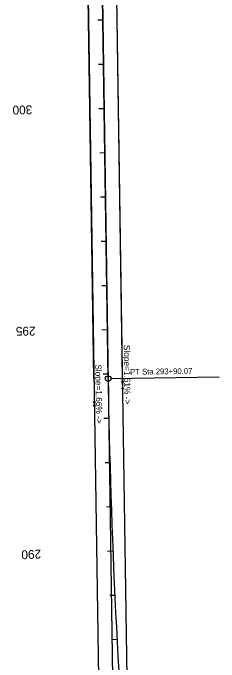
# Model space of a CAD drawing. Extents: x 5180909 to 5237144, y 3695282 to 3720102.
# Drawn here: x 5196575 to 5197040, y 3712197 to 3713664 of the extents above; entities that cross this region are included whole.
import ezdxf

# ---------------------------------------------------------------- set-up
doc = ezdxf.new("R2010")
doc.units = 0
for name, color, linetype in [('Alignment', 7, 'Continuous'), ('Default', 7, 'Continuous'), ('DisFieldPoint', 7, 'Continuous'), ('dsnEntrancePaved', 7, 'Continuous'), ('dsnShadingGranular', 7, 'Continuous'), ('dsnSidewalkShadingRamp', 7, 'Continuous')]:
    doc.layers.add(name, color=color, linetype=linetype)

msp = doc.modelspace()

# ---------------------------------------------------------------- linework, layer by layer
at = {"layer": 'Alignment'}
msp.add_line((5196789.7, 3712837.6), (5196749.6, 3715500.4), dxfattribs=at)
msp.add_arc((5212287.9, 3713070.6), 15500, 180.86138, 188.68311, dxfattribs=at)
at = {"layer": 'Default'}
msp.add_arc((5212287.9, 3713070.6), 15500, 180.86138, 188.68311, dxfattribs=at)
at = {"layer": 'DisFieldPoint'}
for p, q in [((5196833.8, 3712073.4), (5196755.7, 3717289.9)), ((5196769.8, 3712072.4), (5196691.7, 3717288.9)), ((5196801.8, 3712072.9), (5196723.7, 3717289.4))]:
    msp.add_line(p, q, dxfattribs=at)
at = {"layer": 'dsnEntrancePaved'}
for p, q in [((5196789.7, 3712837.6), (5196749.6, 3715500.4)), ((5196822.5, 3712828.7), (5196822.5, 3712832)), ((5196820.9, 3712830.3), (5196824.2, 3712830.3)), ((5196822.7, 3712815.4), (5196822.5, 3712830.3)), ((5196822.7, 3712813.8), (5196822.7, 3712817)), ((5196821.1, 3712815.4), (5196824.4, 3712815.4)), ((5196756.9, 3712784.7), (5196760.2, 3712784.7)), ((5196757.1, 3712776.3), (5196760.3, 3712776.3)), ((5196758.6, 3712783), (5196758.6, 3712786.3)), ((5196758.7, 3712776.3), (5196758.6, 3712784.7)), ((5196758.7, 3712774.7), (5196758.7, 3712778))]:
    msp.add_line(p, q, dxfattribs=at)
for centre in [(5196822.5, 3712830.3), (5196822.7, 3712815.4), (5196758.6, 3712784.7), (5196758.7, 3712776.3)]:
    msp.add_circle(centre, 1.64, dxfattribs=at)
msp.add_arc((5212287.9, 3713070.6), 15500, 180.86138, 188.68311, dxfattribs=at)
at = {"layer": 'dsnShadingGranular'}
for p, q in [((5196757.7, 3712837.1), (5196727.7, 3714828.4)), ((5196822.2, 3712838.1), (5196792.1, 3714838.8))]:
    msp.add_line(p, q, dxfattribs=at)
for radius, end in [(15532, 181.08551), (15467.5, 180.94534)]:
    msp.add_arc((5212287.9, 3713070.6), radius, 180.86138, end, dxfattribs=at)
at = {"layer": 'dsnSidewalkShadingRamp'}
for p, q in [((5196777.5, 3713647.4), (5196766.5, 3713647.2)), ((5196779, 3713547.4), (5196768, 3713547.3)), ((5196780.5, 3713447.4), (5196768.3, 3713447.2)), ((5196782, 3713347.4), (5196771, 3713347.3)), ((5196783.5, 3713247.5), (5196772.5, 3713247.3)), ((5196785, 3713147.5), (5196774, 3713147.3)), ((5196786.5, 3713047.5), (5196775.5, 3713047.3)), ((5196788, 3712947.5), (5196775.8, 3712947.3)), ((5196789.5, 3712847.5), (5196778.5, 3712847.3)), ((5196795.9, 3712837.7), (5197040.3, 3712841.3)), ((5196791.3, 3712747.5), (5196780.3, 3712747.3)), ((5196793.7, 3712647.5), (5196782.7, 3712647.2)), ((5196796.7, 3712547.6), (5196785.8, 3712547.2)), ((5196800.4, 3712447.7), (5196788.2, 3712447.2)), ((5196804.8, 3712347.8), (5196793.8, 3712347.2)), ((5196809.8, 3712247.9), (5196798.8, 3712247.3))]:
    msp.add_line(p, q, dxfattribs=at)
msp.add_circle((5196789.7, 3712837.6), 6.25, dxfattribs=at)

# ---------------------------------------------------------------- texts
at = {"layer": 'dsnEntrancePaved'}
for s, rotation, p in [('Slope=1.61% ->', 270.6491, (5196825.1, 3712913.8)), ('Slope=1.66% ->', 271.0702, (5196760.5, 3712869.8))]:
    msp.add_text(s, height=14, rotation=rotation, dxfattribs=at).set_placement(p)
at = {"layer": 'dsnSidewalkShadingRamp'}
for s, height, rotation, p in [('300', 20, 180.8614, (5196618.1, 3713455)), ('295', 20, 180.8614, (5196625.6, 3712955)), ('PT Sta 293+90.07', 13, 0.8614, (5196839.5, 3712846.3)), ('290', 20, 182.3033, (5196637.9, 3712451.1))]:
    msp.add_text(s, height=height, rotation=rotation, dxfattribs=at).set_placement(p)

doc.saveas('drawing.dxf')
